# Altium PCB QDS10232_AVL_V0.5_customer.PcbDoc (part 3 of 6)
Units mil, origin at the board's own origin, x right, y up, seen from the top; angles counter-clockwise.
Board outline 3500 x 3799 mil, 6 copper layers (Top Layer, GND, INT1, PWR1, PWR2, Bottom Layer), stack 78.834 mil thick; 254 components, 204 nets, 7039 pads, 595 vias.
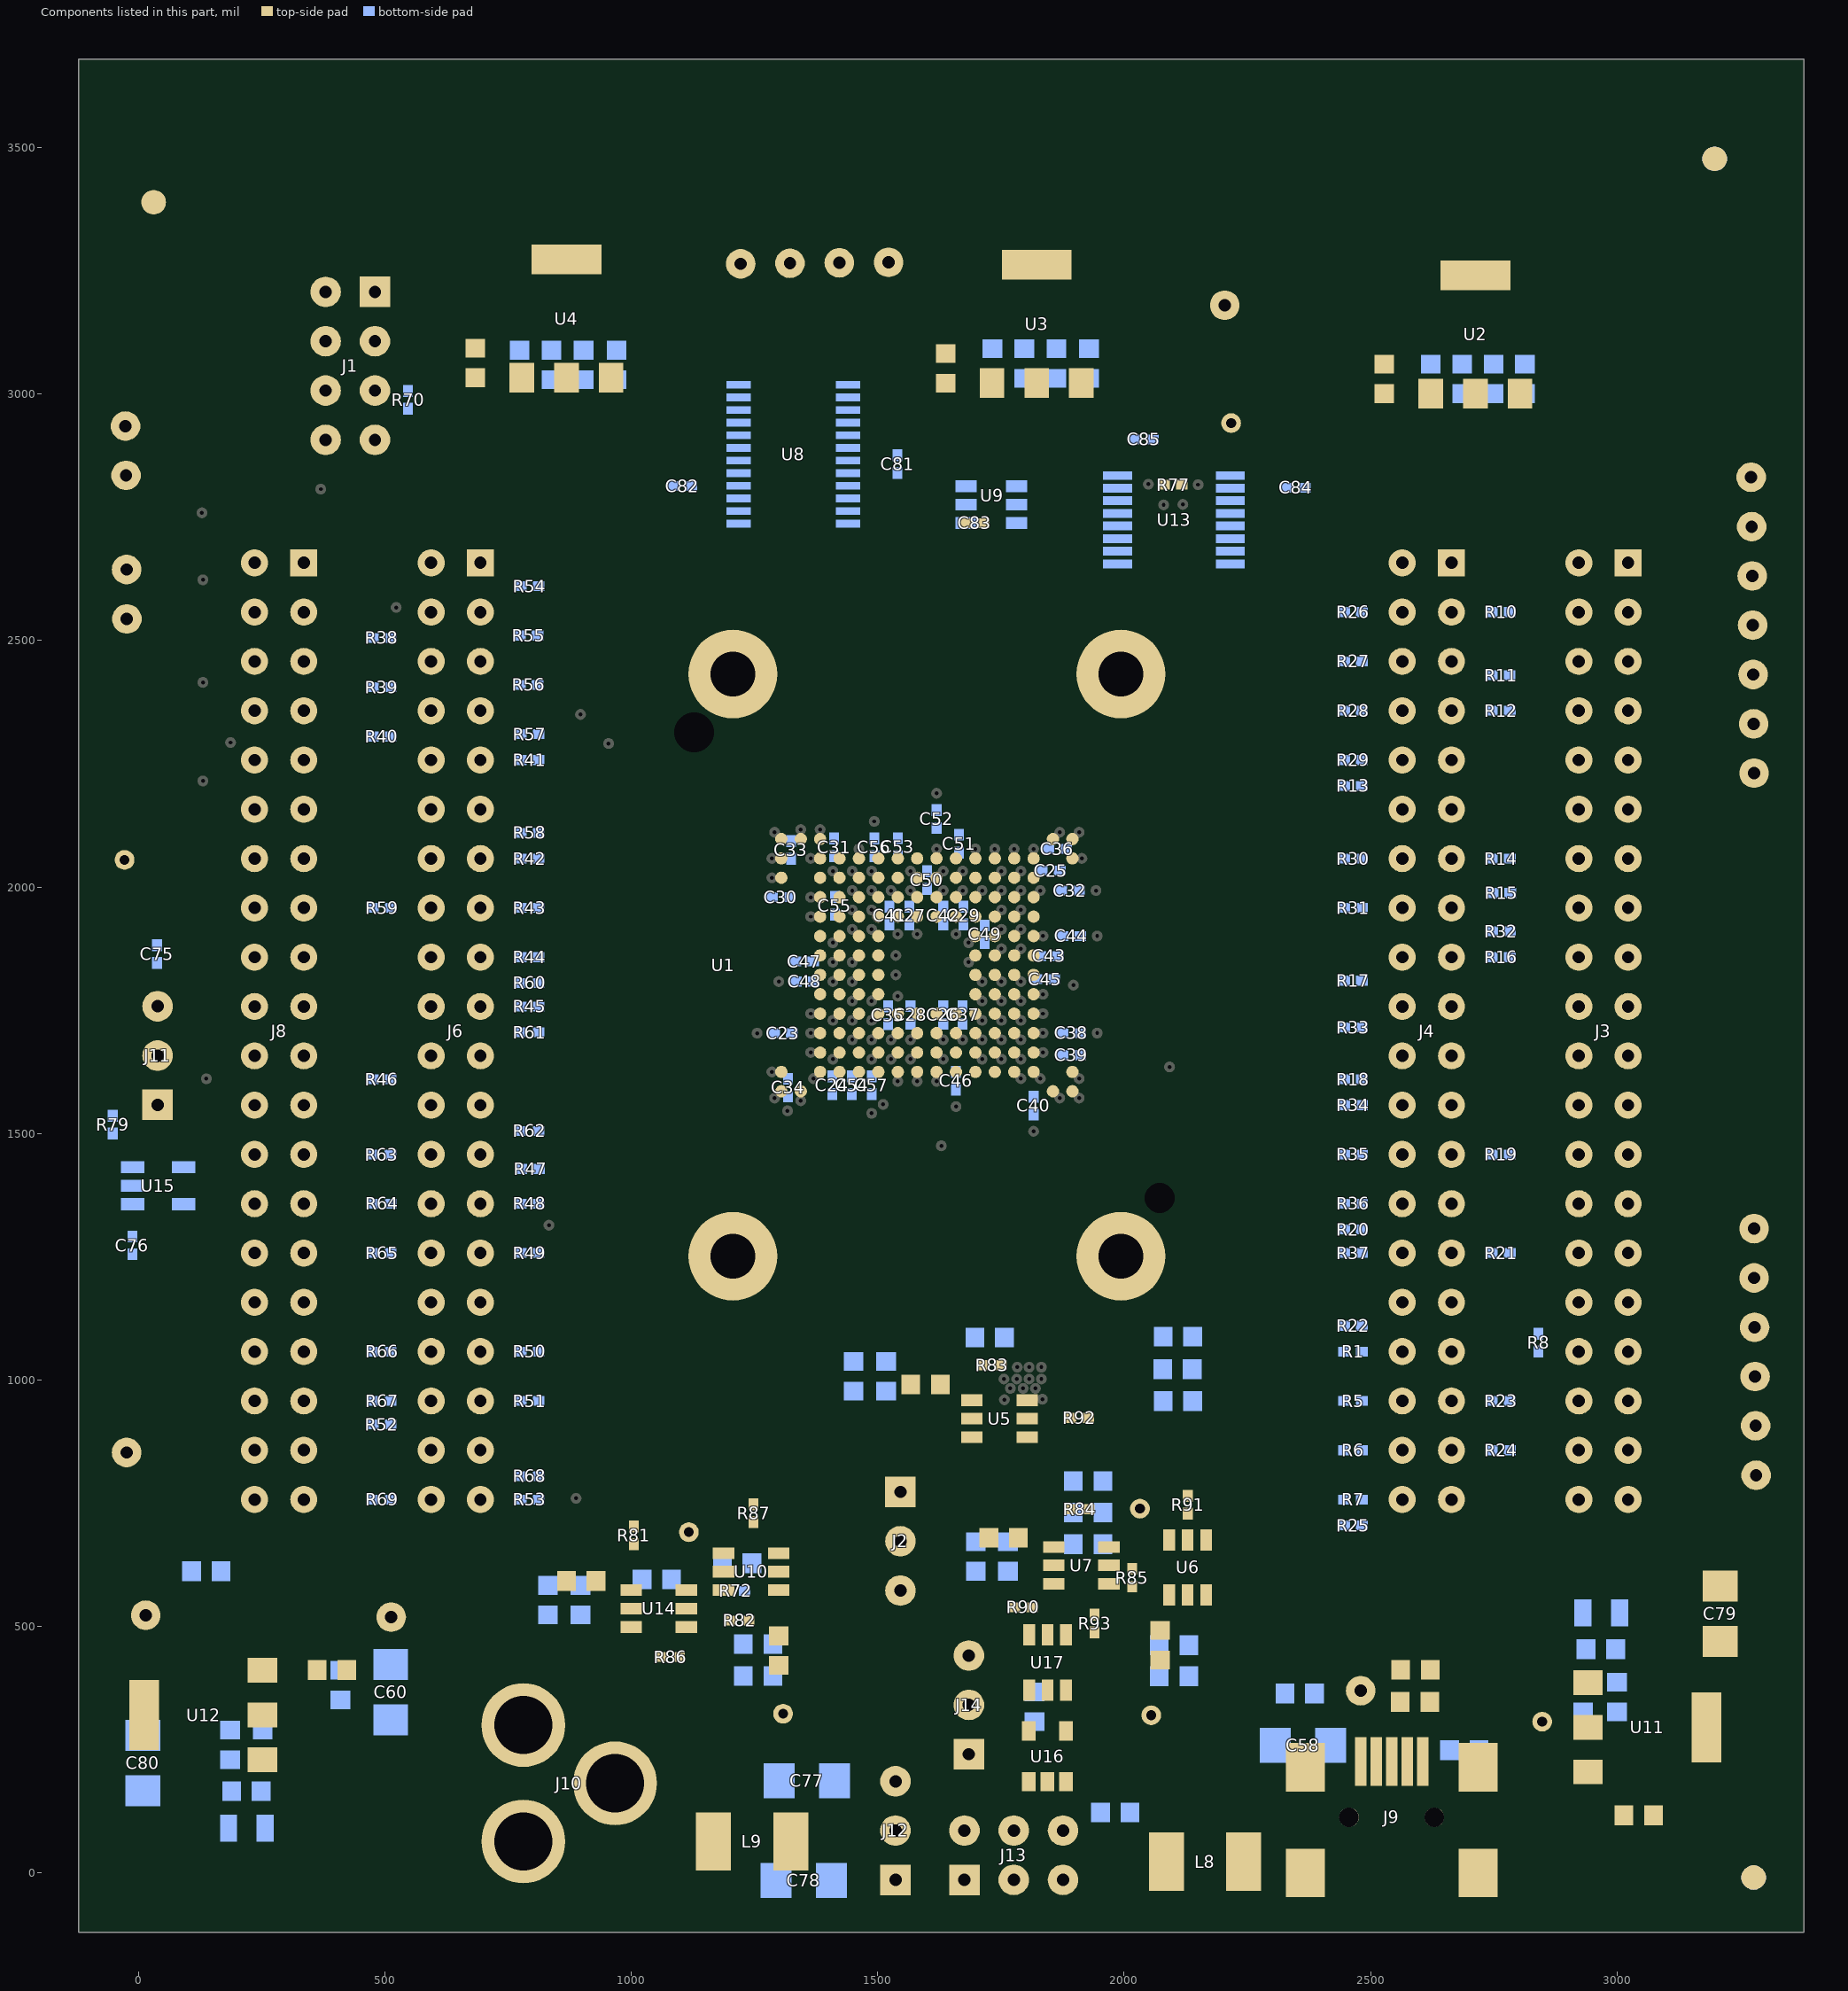
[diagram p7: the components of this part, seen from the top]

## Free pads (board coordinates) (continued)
  round 1.54 on Bottom Overlay: ""(2735.7,3575.61) ""(2735.72,3556.48) ""(2735.72,3556.48) ""(2735.72,3556.48) ""(2735.72,3556.48) ""(2735.79,3579.35) ""(2735.79,3579.35) ""(2735.79,3579.35) ""(2735.79,3579.35) ""(2735.85,3554.11) ""(2735.85,3554.11) ""(2735.85,3554.11) ""(2735.85,3554.11) ""(2736.24,3582.87) ""(2736.24,3582.87) ""(2736.24,3582.87) ""(2736.24,3582.87) ""(2736.25,3576.89) ""(2736.25,3576.89) ""(2736.25,3576.89) ""(2736.25,3576.89) ""(2736.25,3577.98) ""(2736.25,3577.98) ""(2736.25,3577.98) ""(2736.25,3577.98) ""(2736.35,3554.2) ""(2736.35,3554.2) ""(2736.35,3554.2) ""(2736.35,3554.2) ""(2736.52,3567.14) ""(2736.52,3567.14) ""(2736.52,3567.14) ""(2736.52,3567.14) ""(2736.89,3554.39) ""(2736.89,3554.39) ""(2736.89,3554.39) ""(2736.89,3554.39) ""(2737.03,3557.18) ""(2737.03,3557.18) ""(2737.03,3557.18) ""(2737.03,3557.18) ""(2737.46,3557.55) ""(2737.46,3557.55) ""(2737.46,3557.55) ""(2737.46,3557.55) ""(2737.62,3582.18) ""(2737.62,3582.18) ""(2737.62,3582.18) ""(2737.62,3582.18) ""(2737.98,3558.03) ""(2737.98,3558.03) ""(2737.98,3558.03) ""(2737.98,3558.03) ""(2738.17,3555.12) ""(2738.17,3555.12) ""(2738.17,3555.12) ""(2738.17,3555.12) ""(2738.35,3568.42) ""(2738.35,3568.42) ""(2738.35,3568.42) ""(2738.35,3568.42) ""(2738.55,3555.37) ""(2738.55,3555.37) ""(2738.55,3555.37) ""(2738.55,3555.37) ""(2738.62,3559.04) ""(2738.62,3559.04) ""(2738.81,3555.48) ""(2738.81,3555.48) ""(2738.81,3555.48) ""(2738.81,3555.48) ""(2739.07,3555.48) ""(2739.07,3555.48) ""(2739.07,3555.48) ""(2739.07,3555.48) ""(2739.08,3581.17) ""(2739.08,3581.17) ""(2739.08,3581.17) ""(2739.08,3581.17) ""(2739.35,3560.4) ""(2739.35,3560.4) ""(2739.35,3560.4) ""(2739.35,3560.4) ""(2739.38,3555.41) ""(2739.38,3555.41) ""(2739.38,3555.41) ""(2739.38,3555.41) ""(2739.46,3555.39) ""(2739.46,3555.39) ""(2739.59,3561.29) ""(2739.59,3561.29) ""(2739.59,3561.29) ""(2739.59,3561.29) ""(2739.59,3561.29) ""(2739.81,3569.51) ""(2739.81,3569.51) ""(2739.81,3569.51) ""(2739.81,3569.51) ""(2739.89,3555.01) ""(2739.89,3555.01) ""(2739.89,3555.01) ""(2739.89,3555.01) ""(2740.34,3561.86) ""(2740.34,3561.86) ""(2740.34,3561.86) ""(2740.34,3561.86) ""(2740.34,3561.86) ""(2740.5,3554.59) ""(2740.5,3554.59) ""(2740.5,3554.59) ""(2740.54,3579.71) ""(2740.54,3579.71) ""(2740.54,3579.71) ""(2740.54,3579.71) ""(2740.72,3554.57) ""(2740.72,3554.57) ""(2740.72,3554.57) ""(2740.72,3554.57) ""(2740.72,3561.86) ""(2740.72,3561.86) ""(2740.72,3561.86) ""(2740.72,3561.86) ""(2740.99,3570.69) ""(2740.99,3570.69) ""(2740.99,3570.69) ""(2740.99,3570.69) ""(2741.36,3578.35) ""(2741.36,3578.35) ""(2741.36,3578.35) ""(2741.36,3578.35) ""(2741.81,3572.15) ""(2741.81,3572.15) ""(2741.81,3572.15) ""(2741.81,3572.15) ""(2741.99,3574.7) ""(2741.99,3574.7) ""(2741.99,3576.52) ""(2741.99,3576.52) ""(2741.99,3574.7) ""(2741.99,3574.7) ""(2741.99,3576.52) ""(2741.99,3576.52) ""(2742.27,3555.34) ""(2742.27,3555.34) ""(2742.27,3555.34) ""(2742.27,3561.09) ""(2742.27,3561.09) ""(2742.27,3561.09) ""(2742.27,3555.34) ""(2742.27,3555.34) ""(2742.27,3561.09) ""(2742.27,3561.09) ""(2752.59,3555.39) ""(2752.59,3555.39) ""(2752.59,3555.39) ""(2752.59,3555.39) ""(2752.59,3555.69) ""(2752.59,3555.69) ""(2752.59,3555.69) ""(2752.59,3555.69) ""(2753.12,3556.42) ""(2753.12,3556.42) ""(2753.12,3556.42) ""(2753.12,3556.42) ""(2753.36,3554.62) ""(2753.36,3554.62) ""(2753.36,3554.62) ""(2753.36,3554.62) ""(2753.56,3556.57) ""(2753.56,3556.57) ""(2753.56,3556.57) ""(2753.56,3556.57) ""(2754.15,3556.7) ""(2754.15,3556.7) ""(2754.15,3556.7) ""(2754.15,3556.7) ""(2754.45,3556.99) ""(2754.45,3556.99) ""(2754.45,3556.99) ""(2754.45,3556.99) ""(2754.66,3557.25) ""(2754.66,3557.25) ""(2754.66,3557.25) ""(2754.66,3557.25) ""(2754.91,3557.71) ""(2754.91,3557.71) ""(2754.91,3557.71) ""(2754.91,3557.71) ""(2755.04,3558.22) ""(2755.04,3558.22) ""(2755.04,3558.22) ""(2755.04,3558.22) ""(2755.04,3570.35) ""(2755.04,3570.35) ""(2755.04,3570.35) ""(2755.04,3570.35) ""(2755.06,3570.91) ""(2755.06,3570.91) ""(2755.06,3570.91) ""(2755.06,3570.91) ""(2755.17,3571.3) ""(2755.17,3571.3) ""(2755.17,3571.3) ""(2755.17,3571.3) ""(2755.61,3572.37) ""(2755.61,3572.37) ""(2755.61,3572.37) ""(2755.61,3572.37) ""(2756.07,3573.17) ""(2756.07,3573.17) ""(2756.07,3573.17) ""(2756.07,3573.17) ""(2756.51,3573.64) ""(2756.51,3573.64) ""(2756.51,3573.64) ""(2756.51,3573.64) ""(2757.69,3574.29) ""(2757.69,3574.29) ""(2757.69,3574.29) ""(2757.69,3574.29) ""(2759.33,3574.8) ""(2759.33,3574.8) ""(2759.33,3574.8) ""(2759.33,3574.8) ""(2760.98,3574.8) ""(2760.98,3574.8) ""(2760.98,3574.8) ""(2760.98,3574.8) ""(2761.02,3557.93) ""(2761.02,3557.93) ""(2761.06,3557.37) ""(2761.06,3557.37) ""(2761.06,3569.53) ""(2761.06,3569.53) ""(2761.06,3557.37) ""(2761.06,3557.37) ""(2761.06,3569.53) ""(2761.06,3569.53) ""(2761.23,3557.12) ""(2761.23,3557.12) ""(2761.23,3557.12) ""(2761.23,3557.12) ""(2761.23,3570.04) ""(2761.23,3570.04) ""(2761.23,3570.04) ""(2761.23,3570.04) ""(2761.27,3554.62) ""(2761.27,3554.62) ""(2761.27,3554.62) ""(2761.27,3554.62) ""(2761.44,3570.38) ""(2761.44,3570.38) ""(2761.44,3570.38) ""(2761.44,3570.38) ""(2761.53,3556.78) ""(2761.53,3556.78) ""(2761.53,3556.78) ""(2761.53,3556.78) ""(2761.7,3556.7) ""(2761.7,3556.7) ""(2761.7,3556.7) ""(2761.7,3556.7) ""(2761.78,3570.89) ""(2761.78,3570.89) ""(2761.78,3570.89) ""(2761.78,3570.89) ""(2762.23,3554.62) ""(2762.23,3554.62) ""(2762.23,3554.62) ""(2762.23,3554.62) ""(2762.23,3556.7) ""(2762.23,3556.7) ""(2762.23,3556.7) ""(2762.23,3556.7) ""(2762.33,3571.27) ""(2762.33,3571.27) ""(2762.33,3571.27) ""(2762.33,3571.27) ""(2762.93,3574.56) ""(2762.93,3574.56) ""(2762.93,3574.56) ""(2762.93,3574.56) ""(2762.97,3571.61) ""(2762.97,3571.61) ""(2762.97,3571.61) ""(2762.97,3571.61) ""(2763,3555.39) ""(2763,3555.39) ""(2763,3555.39) ""(2763,3555.39) ""(2763,3555.93) ""(2763,3555.93) ""(2763,3555.93) ""(2763,3555.93) ""(2763.57,3574.48) ""(2763.57,3574.48) ""(2763.57,3574.48) ""(2763.57,3574.48) ""(2763.78,3571.79) ""(2763.78,3571.79) ""(2763.78,3571.79) ""(2763.78,3571.79) ""(2764.26,3571.74) ""(2764.26,3571.74) ""(2764.26,3571.74) ""(2764.26,3571.74) ""(2764.36,3574.25) ""(2764.36,3574.25) ""(2764.36,3574.25) ""(2764.36,3574.25) ""(2764.54,3555.35) ""(2764.54,3555.35) ""(2764.54,3555.35) ""(2764.54,3555.35) ""(2764.54,3555.74) ""(2764.54,3555.74) ""(2764.54,3555.74) ""(2764.54,3555.74) ""(2764.56,3571.7) ""(2764.56,3571.7) ""(2764.56,3571.7) ""(2764.56,3571.7) ""(2764.9,3571.56) ""(2764.9,3571.56) ""(2764.9,3571.56) ""(2764.9,3571.56) ""(2765,3573.94) ""(2765,3573.94) ""(2765,3573.94) ""(2765,3573.94) ""(2765.15,3571.39) ""(2765.15,3571.39) ""(2765.15,3571.39) ""(2765.15,3571.39) ""(2765.23,3556.51) ""(2765.23,3556.51) ""(2765.23,3556.51) ""(2765.23,3556.51) ""(2765.31,3554.58) ""(2765.43,3571.2) ""(2765.43,3571.2) ""(2765.43,3571.2) ""(2765.43,3571.2) ""(2765.58,3573.57) ""(2765.58,3573.57) ""(2765.58,3573.57) ""(2765.58,3573.57) ""(2765.7,3571.14) ""(2765.7,3571.14) ""(2765.7,3571.14) ""(2765.7,3571.14) ""(2765.85,3556.57) ""(2765.85,3556.57) ""(2765.85,3556.57) ""(2765.85,3556.57) ""(2765.96,3571.21) ""(2765.96,3571.21) ""(2765.96,3571.21) ""(2765.96,3571.21) ""(2766.05,3573.24) ""(2766.05,3573.24) ""(2766.05,3573.24) ""(2766.05,3573.24) ""(2766.23,3556.66) ""(2766.23,3556.66) ""(2766.23,3556.66) ""(2766.23,3556.66) ""(2766.31,3572.89) ""(2766.31,3572.89) ""(2766.31,3572.89) ""(2766.31,3572.89) ""(2766.35,3571.18) ""(2766.35,3571.18) ""(2766.35,3571.18) ""(2766.35,3571.18) ""(2766.44,3556.87) ""(2766.44,3556.87) ""(2766.44,3556.87) ""(2766.44,3556.87) ""(2766.57,3572.5) ""(2766.57,3572.5) ""(2766.57,3572.5) ""(2766.57,3572.5) ""(2766.6,3570.96) ""(2766.6,3570.96) ""(2766.6,3570.96) ""(2766.6,3570.96) ""(2766.65,3572.43) ""(2766.65,3572.43) ""(2766.65,3572.43) ""(2766.65,3572.43) ""(2766.7,3557.16) ""(2766.7,3557.16) ""(2766.7,3557.16) ""(2766.7,3557.16) ""(2766.8,3570.65) ""(2766.8,3570.65) ""(2766.8,3570.65) ""(2766.8,3570.65) ""(2766.82,3572.33) ""(2766.82,3572.33) ""(2766.82,3572.33) ""(2766.82,3572.33) ""(2766.82,3557.59) ""(2766.82,3557.59) ""(2766.82,3557.59) ""(2766.82,3557.59) ""(2766.91,3558.14) ""(2766.91,3558.14) ""(2766.91,3569.02) ""(2766.91,3569.02) ""(2766.91,3570.34) ""(2766.91,3570.34) ""(2766.91,3558.14) ""(2766.91,3558.14) ""(2766.91,3569.02) ""(2766.91,3569.02) ""(2766.91,3570.34) ""(2766.91,3570.34) ""(2766.94,3572.29) ""(2766.94,3572.29) ""(2766.94,3572.29) ""(2766.94,3572.29) ""(2767.04,3572.28) ""(2767.04,3572.28) ""(2767.04,3572.28) ""(2767.04,3572.28) ""(2767.16,3572.3) ""(2767.16,3572.3) ""(2767.16,3572.3) ""(2767.16,3572.3) ""(2767.28,3572.49) ""(2767.28,3572.49) ""(2767.28,3572.49) ""(2767.28,3572.49) ""(2767.3,3572.58) ""(2767.3,3572.58) ""(2767.3,3572.58) ""(2767.3,3572.58) ""(2767.3,3573.38) ""(2767.3,3573.38) ""(2767.3,3573.38) ""(2767.3,3573.38) ""(2768.07,3574.15) ""(2768.07,3574.15) ""(2768.07,3574.15) ""(2768.07,3574.15) ""(2773.06,3558.65) ""(2773.06,3558.65) ""(2773.06,3558.65) ""(2773.06,3558.65) ""(2773.06,3570.42) ""(2773.06,3570.42) ""(2773.06,3570.42) ""(2773.06,3570.42) ""(2773.14,3570.84) ""(2773.14,3570.84) ""(2773.18,3557.67) ""(2773.18,3557.67) ""(2773.35,3557.33) ""(2773.35,3557.33) ""(2773.35,3557.33) ""(2773.35,3557.33) ""(2773.39,3571.23) ""(2773.39,3571.23) ""(2773.39,3571.23) ""(2773.39,3571.23) ""(2773.73,3556.99) ""(2773.73,3556.99) ""(2773.73,3556.99) ""(2773.73,3556.99) ""(2773.78,3571.52) ""(2773.78,3571.52) ""(2773.78,3571.52) ""(2773.78,3571.52) ""(2774.16,3571.69) ""(2774.16,3571.69) ""(2774.16,3571.69) ""(2774.16,3571.69) ""(2774.2,3556.66) ""(2774.2,3556.66) ""(2774.2,3556.66) ""(2774.2,3556.66) ""(2774.45,3554.58) ""(2774.45,3554.58) ""(2774.45,3554.58) ""(2774.45,3554.58) ""(2774.67,3571.78) ""(2774.67,3571.78) ""(2774.67,3571.78) ""(2774.67,3571.78) ""(2774.71,3556.47) ""(2774.71,3556.47) ""(2774.71,3556.47) ""(2774.71,3556.47) ""(2775.01,3571.86) ""(2775.01,3571.86) ""(2775.01,3571.86) ""(2775.01,3571.86) ""(2775.13,3574.06) ""(2775.13,3574.06) ""(2775.13,3574.06) ""(2775.13,3574.06) ""(2775.18,3572.03) ""(2775.18,3572.03) ""(2775.18,3572.03) ""(2775.18,3572.03) ""(2775.22,3555.35) ""(2775.22,3555.35) ""(2775.22,3555.35) ""(2775.22,3555.35) ""(2775.22,3555.75) ""(2775.22,3555.75) ""(2775.22,3555.75) ""(2775.22,3555.75) ""(2775.26,3572.37) ""(2775.26,3572.37) ""(2775.26,3572.37) ""(2775.26,3572.37) ""(2775.26,3573.81) ""(2775.26,3573.81) ""(2775.26,3573.81) ""(2775.26,3573.81) ""(2778.64,3574.09) ""(2778.64,3574.09) ""(2778.64,3574.09) ""(2778.64,3574.09) ""(2778.78,3575.82) ""(2778.78,3575.82) ""(2778.78,3575.82) ""(2778.78,3575.82) ""(2779.05,3552.78) ""(2779.05,3552.78) ""(2779.05,3576.31) ""(2779.05,3576.31) ""(2779.05,3552.78) ""(2779.05,3552.78) ""(2779.05,3576.31) ""(2779.05,3576.31) ""(2779.19,3551.4) ""(2779.19,3551.4) ""(2779.19,3551.4) ""(2779.19,3551.4) ""(2779.26,3572.78) ""(2779.26,3572.78) ""(2779.26,3572.78) ""(2779.26,3572.78) ""(2779.4,3554.51) ""(2779.4,3554.51) ""(2779.4,3554.51) ""(2779.4,3554.51) ""(2779.61,3572.57) ""(2779.61,3572.57) ""(2779.61,3572.57) ""(2779.61,3572.57) ""(2779.68,3576.86) ""(2779.68,3576.86) ""(2779.68,3576.86) ""(2779.68,3576.86) ""(2779.74,3549.88) ""(2779.74,3549.88) ""(2779.74,3549.88) ""(2779.74,3549.88) ""(2779.95,3555.41) ""(2779.95,3555.41) ""(2779.95,3555.41) ""(2779.95,3555.41) ""(2780.23,3572.43) ""(2780.23,3572.43) ""(2780.23,3577.27) ""(2780.23,3577.27) ""(2780.23,3572.43) ""(2780.23,3572.43) ""(2780.23,3577.27) ""(2780.23,3577.27) ""(2780.44,3566.55) ""(2780.44,3566.55) ""(2780.44,3566.55) ""(2780.44,3566.55) ""(2780.58,3568.14) ""(2780.58,3568.14) ""(2780.58,3568.14) ""(2780.58,3568.14) ""(2780.64,3564.96) ""(2780.64,3564.96) ""(2780.64,3564.96) ""(2780.64,3564.96) ""(2780.78,3569.53) ""(2780.78,3569.53) ""(2780.78,3569.53) ""(2780.78,3569.53) ""(2780.92,3572.43) ""(2780.92,3572.43) ""(2780.92,3572.43) ""(2780.92,3572.43) ""(2780.92,3577.55) ""(2780.92,3577.55) ""(2780.92,3577.55) ""(2780.92,3577.55) ""(2780.99,3548.35) ""(2780.99,3548.35) ""(2780.99,3548.35) ""(2780.99,3548.35) ""(2781.27,3556.66) ""(2781.27,3556.66) ""(2781.27,3556.66) ""(2781.27,3556.66) ""(2781.27,3563.3) ""(2781.27,3563.3) ""(2781.27,3563.3) ""(2781.27,3563.3) ""(2781.41,3572.43) ""(2781.41,3572.43) ""(2781.41,3572.43) ""(2781.41,3572.43) ""(2781.48,3570.77) ""(2781.48,3570.77) ""(2781.48,3570.77) ""(2781.48,3570.77) ""(2781.75,3572.64) ""(2781.75,3572.64) ""(2781.75,3572.64) ""(2781.75,3572.64) ""(2781.89,3573.12) ""(2781.89,3573.12) ""(2781.89,3573.12) ""(2781.89,3573.12) ""(2781.89,3573.4) ""(2781.89,3573.4) ""(2781.89,3573.4) ""(2781.89,3573.4) ""(2781.96,3562.47) ""(2781.96,3562.47) ""(2781.96,3573.68) ""(2781.96,3573.68) ""(2781.96,3562.47) ""(2781.96,3562.47) ""(2781.96,3573.68) ""(2781.96,3573.68) ""(2782.1,3571.53) ""(2782.1,3571.53) ""(2782.1,3571.53) ""(2782.1,3571.53) ""(2782.1,3577.48) ""(2782.1,3577.48) ""(2782.1,3577.48) ""(2782.1,3577.48) ""(2782.38,3574.02) ""(2782.38,3574.02) ""(2782.38,3574.02) ""(2782.38,3574.02) ""(2782.72,3557.49) ""(2782.72,3557.49) ""(2782.72,3557.49) ""(2782.72,3557.49) ""(2782.79,3546.97) ""(2782.79,3546.97) ""(2782.79,3546.97) ""(2782.79,3546.97) ""(2782.79,3574.02) ""(2782.79,3574.02) ""(2782.79,3574.02) ""(2782.79,3574.02) ""(2782.79,3577.27) ""(2782.79,3577.27) ""(2782.79,3577.27) ""(2782.79,3577.27) ""(2783.07,3572.22) ""(2783.07,3572.22) ""(2783.07,3572.22) ""(2783.07,3572.22) ""(2783.07,3573.75) ""(2783.07,3573.75) ""(2783.07,3573.75) ""(2783.07,3573.75) ""(2783.34,3576.86) ""(2783.34,3576.86) ""(2783.35,3576.86) ""(2783.35,3576.86) ""(2783.41,3561.15) ""(2783.41,3561.15) ""(2783.41,3561.15) ""(2783.41,3561.15) ""(2783.9,3557.97) ""(2783.9,3557.97) ""(2783.9,3557.97) ""(2783.9,3557.97) ""(2783.9,3576.31) ""(2783.9,3576.31) ""(2783.9,3576.31) ""(2783.9,3576.31) ""(2784.25,3574.02) ""(2784.25,3574.02) ""(2784.25,3574.02) ""(2784.25,3574.02) ""(2784.25,3574.58) ""(2784.25,3574.58) ""(2784.25,3574.58) ""(2784.25,3574.58) ""(2784.25,3575.48) ""(2784.25,3575.48) ""(2784.25,3575.48) ""(2784.25,3575.48) ""(2784.38,3573.75) ""(2784.38,3573.75) ""(2784.38,3573.75) ""(2784.38,3573.75) ""(2784.45,3546.14) ""(2784.45,3546.14) ""(2784.45,3546.14) ""(2784.45,3546.14) ""(2784.73,3550.43) ""(2784.73,3550.43) ""(2784.73,3573.61) ""(2784.73,3573.61) ""(2784.73,3550.43) ""(2784.73,3550.43) ""(2784.73,3573.61) ""(2784.73,3573.61) ""(2784.8,3551.05) ""(2784.8,3551.05) ""(2784.8,3551.05) ""(2784.8,3551.05) ""(2784.87,3560.25) ""(2784.87,3560.25) ""(2784.87,3560.25) ""(2784.87,3560.25) ""(2784.94,3551.61) ""(2784.94,3551.61) ""(2784.94,3551.61) ""(2784.94,3551.61) ""(2785.01,3549.95) ""(2785.01,3549.95) ""(2785.01,3549.95) ""(2785.01,3549.95) ""(2785.22,3551.95) ""(2785.22,3551.95) ""(2785.22,3551.95) ""(2785.22,3551.95) ""(2785.42,3573.95) ""(2785.42,3573.95) ""(2785.42,3573.95) ""(2785.42,3573.95) ""(2785.56,3549.39) ""(2785.56,3549.39) ""(2785.56,3549.39) ""(2785.56,3549.39) ""(2785.77,3552.37) ""(2785.77,3552.37) ""(2786.18,3548.91) ""(2786.18,3548.91) ""(2786.18,3548.91) ""(2786.18,3548.91) ""(2786.32,3558.25) ""(2786.32,3558.25) ""(2786.32,3558.25) ""(2786.32,3558.25) ""(2786.46,3574.78) ""(2786.46,3574.78) ""(2786.46,3574.78) ""(2786.46,3574.78) ""(2786.81,3559.91) ""(2786.81,3559.91) ""(2786.81,3559.91) ""(2786.81,3559.91) ""(2786.88,3564.54) ""(2786.88,3564.54) ""(2786.88,3564.54) ""(2786.88,3564.54) ""(2786.88,3569.53) ""(2786.88,3569.53) ""(2786.88,3569.53) ""(2786.88,3569.53) ""(2786.89,3570.47) ""(2786.89,3570.47) ""(2786.89,3570.47) ""(2786.89,3570.47) ""(2786.95,3545.73) ""(2786.95,3545.73) ""(2786.95,3574.92) ""(2786.95,3574.92) ""(2786.95,3545.73) ""(2786.95,3545.73) ""(2786.95,3574.92) ""(2786.95,3574.92) ""(2787.02,3548.49) ""(2787.02,3548.49) ""(2787.02,3548.49) ""(2787.02,3548.49) ""(2787.06,3571.19) ""(2787.06,3571.19) ""(2787.06,3571.19) ""(2787.06,3571.19) ""(2787.08,3563.47) ""(2787.08,3563.47) ""(2787.08,3563.47) ""(2787.08,3563.47) ""(2787.08,3553.2) ""(2787.08,3553.2) ""(2787.08,3553.2) ""(2787.08,3553.2) ""(2787.29,3562.92) ""(2787.29,3562.92) ""(2787.29,3562.92) ""(2787.29,3562.92) ""(2787.38,3571.97) ""(2787.38,3571.97) ""(2787.38,3571.97) ""(2787.38,3571.97) ""(2787.66,3562.43) ""(2787.66,3562.43) ""(2787.66,3562.43) ""(2787.66,3562.43) ""(2787.78,3572.42) ""(2787.78,3572.42) ""(2787.78,3572.42) ""(2787.78,3572.42) ""(2787.93,3562.15) ""(2787.93,3562.15) ""(2787.93,3562.15) ""(2787.93,3562.15) ""(2788.05,3548.15) ""(2788.05,3548.15) ""(2788.05,3548.15) ""(2788.05,3548.15) ""(2788.19,3553.47) ""(2788.19,3553.47) ""(2788.19,3553.47) ""(2788.19,3553.47) ""(2788.26,3575.34) ""(2788.26,3575.34) ""(2788.26,3575.34) ""(2788.26,3575.34) ""(2788.33,3561.9) ""(2788.33,3561.9) ""(2788.33,3561.9) ""(2788.33,3561.9) ""(2788.35,3572.73) ""(2788.35,3572.73) ""(2788.35,3572.73) ""(2788.35,3572.73) ""(2788.4,3559.63) ""(2788.4,3559.63) ""(2788.4,3559.63) ""(2788.4,3559.63) ""(2789.01,3572.88) ""(2789.01,3572.88) ""(2789.01,3572.88) ""(2789.01,3572.88) ""(2789.09,3547.87) ""(2789.09,3547.87) ""(2789.09,3547.87) ""(2789.09,3547.87) ""(2789.16,3545.59) ""(2789.16,3545.59) ""(2789.16,3545.59) ""(2789.16,3545.59) ""(2789.3,3553.61) ""(2789.3,3553.61) ""(2789.3,3558.25) ""(2789.3,3558.25) ""(2789.3,3553.61) ""(2789.3,3553.61) ""(2789.3,3558.25) ""(2789.3,3558.25) ""(2789.44,3561.71) ""(2789.44,3561.71) ""(2789.44,3561.71) ""(2789.44,3561.71) ""(2789.5,3572.88) ""(2789.5,3572.88) ""(2789.5,3572.88) ""(2789.5,3572.88) ""(2790.06,3559.7) ""(2790.06,3559.7) ""(2790.06,3559.7) ""(2790.06,3559.7) ""(2790.06,3575.34) ""(2790.06,3575.34) ""(2790.06,3575.34) ""(2790.06,3575.34) ""(2790.07,3572.73) ""(2790.07,3572.73) ""(2790.07,3572.73) ""(2790.07,3572.73) ""(2790.13,3547.59) ""(2790.13,3547.59) ""(2790.13,3553.68) ""(2790.13,3553.68) ""(2790.13,3547.59) ""(2790.13,3547.59) ""(2790.13,3553.68) ""(2790.13,3553.68) ""(2790.2,3561.91) ""(2790.2,3561.91) ""(2790.2,3561.91) ""(2790.2,3561.91) ""(2790.66,3572.5) ""(2790.66,3572.5) ""(2790.66,3572.5) ""(2790.66,3572.5) ""(2790.76,3562.4) ""(2790.76,3562.4) ""(2790.76,3562.4) ""(2790.76,3562.4) ""(2791.07,3572.27) ""(2791.07,3572.27) ""(2791.07,3572.27) ""(2791.07,3572.27) ""(2791.1,3558.04) ""(2791.1,3558.04) ""(2791.1,3558.04) ""(2791.1,3558.04) ""(2791.17,3562.81) ""(2791.17,3562.81) ""(2791.17,3562.81) ""(2791.17,3562.81) ""(2791.24,3553.61) ""(2791.24,3553.61) ""(2791.24,3553.61) ""(2791.24,3553.61) ""(2791.38,3547.52) ""(2791.38,3547.52) ""(2791.38,3547.52) ""(2791.38,3547.52) ""(2791.38,3571.86) ""(2791.38,3571.86) ""(2791.39,3571.86) ""(2791.39,3571.86) ""(2791.59,3559.84) ""(2791.59,3559.84) ""(2791.59,3559.84) ""(2791.59,3559.84) ""(2791.59,3563.51) ""(2791.59,3563.51) ""(2791.59,3563.51) ""(2791.59,3563.51) ""(2791.64,3571.4) ""(2791.64,3571.4) ""(2791.64,3571.4) ""(2791.64,3571.4) ""(2791.66,3545.86) ""(2791.66,3545.86) ""(2791.66,3545.86) ""(2791.66,3545.86) ""(2791.72,3571) ""(2791.72,3571) ""(2791.72,3571) ""(2791.72,3571) ""(2791.72,3564.27) ""(2791.72,3564.27) ""(2791.72,3570.43) ""(2791.72,3570.43) ""(2791.72,3564.27) ""(2791.72,3564.27) ""(2791.72,3570.43) ""(2791.72,3570.43) ""(2792.35,3547.87) ""(2792.35,3547.87) ""(2792.35,3547.87) ""(2792.35,3547.87) ""(2792.35,3557.83) ""(2792.35,3557.83) ""(2792.35,3557.83) ""(2792.35,3557.83) ""(2792.35,3560.05) ""(2792.35,3560.05) ""(2792.35,3560.05) ""(2792.35,3560.05) ""(2792.49,3575.2) ""(2792.49,3575.2) ""(2792.49,3575.2) ""(2792.49,3575.2) ""(2792.56,3550.15) ""(2792.56,3550.15) ""(2792.56,3550.15) ""(2792.56,3550.15) ""(2792.56,3550.98) ""(2792.56,3550.98) ""(2792.56,3550.98) ""(2792.56,3550.98) ""(2792.76,3548.22) ""(2792.76,3548.22) ""(2792.76,3549.81) ""(2792.76,3549.81) ""(2792.76,3551.4) ""(2792.76,3551.4) ""(2792.76,3553.41) ""(2792.76,3553.41) ""(2792.76,3559.84) ""(2792.76,3559.84) ""(2792.76,3548.22) ""(2792.76,3548.22) ""(2792.76,3549.81) ""(2792.76,3549.81) ""(2792.76,3551.4) ""(2792.76,3551.4) ""(2792.76,3553.41) ""(2792.76,3553.41) ""(2792.76,3559.84) ""(2792.76,3559.84) ""(2792.97,3548.49) ""(2792.97,3548.49) ""(2792.97,3548.49) ""(2792.97,3548.49) ""(2792.97,3549.18) ""(2792.97,3549.18) ""(2792.97,3549.18) ""(2792.97,3549.18) ""(2793.04,3551.74) ""(2793.04,3551.74) ""(2793.04,3551.74) ""(2793.04,3551.74) ""(2793.11,3548.91) ""(2793.11,3548.91) ""(2793.11,3548.91) ""(2793.11,3548.91) ""(2793.46,3574.64) ""(2793.46,3574.64) ""(2793.46,3574.64) ""(2793.46,3574.64) ""(2793.52,3557.56) ""(2793.52,3557.56) ""(2793.52,3557.56) ""(2793.52,3557.56) ""(2793.66,3552.23) ""(2793.66,3552.23) ""(2793.66,3552.23) ""(2793.66,3552.23) ""(2793.8,3546.14) ""(2793.8,3546.14) ""(2793.8,3546.14) ""(2793.8,3546.14) ""(2794.01,3553.2) ""(2794.01,3553.2) ""(2794.01,3553.2) ""(2794.01,3553.2) ""(2794.01,3557.35) ""(2794.01,3557.35) ""(2794.01,3557.35) ""(2794.01,3557.35) ""(2794.29,3557.42) ""(2794.29,3557.42) ""(2794.29,3557.42) ""(2794.29,3557.42) ""(2794.29,3557.9) ""(2794.29,3557.9) ""(2794.29,3557.9) ""(2794.29,3557.9) ""(2794.36,3552.44) ""(2794.36,3552.44) ""(2794.36,3552.44) ""(2794.36,3552.44) ""(2794.42,3557.63) ""(2794.42,3557.63) ""(2794.42,3557.63) ""(2794.42,3557.63) ""(2794.84,3552.99) ""(2794.84,3552.99) ""(2794.84,3552.99) ""(2794.84,3552.99) ""(2794.84,3560.74) ""(2794.84,3560.74) ""(2794.84,3560.74) ""(2794.84,3560.74) ""(2794.91,3552.51) ""(2794.91,3552.51) ""(2794.91,3552.51) ""(2794.91,3552.51) ""(2794.98,3560.39) ""(2794.98,3560.39) ""(2794.98,3560.39) ""(2794.98,3560.39) ""(2794.98,3573.88) ""(2794.98,3573.88) ""(2794.98,3573.88) ""(2794.98,3573.88) ""(2795.05,3561.08) ""(2795.05,3561.08) ""(2795.05,3561.08) ""(2795.05,3561.08) ""(2795.12,3546.42) ""(2795.12,3546.42) ""(2795.12,3546.42) ""(2795.12,3546.42) ""(2795.32,3561.43) ""(2795.32,3561.43) ""(2795.32,3561.43) ""(2795.32,3561.43) ""(2795.74,3552.37) ""(2795.74,3552.37) ""(2795.74,3552.37) ""(2795.74,3552.37) ""(2795.81,3552.85) ""(2795.81,3552.85) ""(2796.02,3572.85) ""(2796.02,3572.85) ""(2796.02,3572.85) ""(2796.02,3572.85) ""(2796.16,3562.12) ""(2796.16,3562.12) ""(2796.16,3562.12) ""(2796.16,3562.12) ""(2796.43,3547.18) ""(2796.43,3547.18) ""(2796.43,3547.18) ""(2796.43,3547.18) ""(2796.5,3552.02) ""(2796.5,3552.02) ""(2796.5,3552.02) ""(2796.5,3552.02) ""(2796.71,3552.71) ""(2796.71,3552.71) ""(2796.71,3552.71) ""(2796.71,3552.71) ""(2796.85,3563.09) ""(2796.85,3563.09) ""(2796.85,3563.09) ""(2796.85,3563.09) ""(2797.06,3547.8) ""(2797.06,3547.8) ""(2797.06,3571.6) ""(2797.06,3571.6) ""(2797.06,3547.8) ""(2797.06,3547.8) ""(2797.06,3571.6) ""(2797.06,3571.6) ""(2797.19,3551.68) ""(2797.19,3551.68) ""(2797.19,3551.68) ""(2797.19,3551.68) ""(2797.33,3563.85) ""(2797.33,3563.85) ""(2797.33,3563.85) ""(2797.33,3563.85) ""(2797.61,3548.29) ""(2797.61,3548.29) ""(2797.61,3548.29) ""(2797.61,3548.29) ""(2797.75,3552.44) ""(2797.75,3552.44) ""(2797.75,3552.44) ""(2797.75,3552.44) ""(2797.75,3564.68) ""(2797.75,3564.68) ""(2797.75,3564.68) ""(2797.75,3564.68) ""(2797.75,3570.49) ""(2797.75,3570.49) ""(2797.75,3570.49) ""(2797.75,3570.49) ""(2797.89,3551.19) ""(2797.89,3551.19) ""(2797.89,3551.19) ""(2797.89,3551.19) ""(2797.96,3549.18) ""(2797.96,3549.18) ""(2797.96,3549.18) ""(2797.96,3549.18) ""(2798.09,3550.15) ""(2798.09,3550.15) ""(2798.09,3550.64) ""(2798.09,3550.64) ""(2798.09,3566) ""(2798.09,3566) ""(2798.1,3550.15) ""(2798.1,3550.15) ""(2798.1,3550.64) ""(2798.1,3550.64) ""(2798.1,3566) ""(2798.1,3566) ""(2798.16,3569.11) ""(2798.16,3569.11) ""(2798.16,3569.11) ""(2798.16,3569.11) ""(2798.23,3552.51) ""(2798.23,3552.51) ""(2798.23,3552.51) ""(2798.23,3552.51) ""(2798.23,3567.59) ""(2798.23,3567.59) ""(2798.23,3567.59) ""(2798.23,3567.59) ""(2798.86,3552.78) ""(2798.86,3552.78) ""(2798.86,3552.78) ""(2798.86,3552.78) ""(2799.06,3555.07) ""(2799.06,3555.07) ""(2799.06,3555.07) ""(2799.06,3555.07) ""(2799.13,3553.06) ""(2799.13,3553.06) ""(2799.13,3553.06) ""(2799.13,3553.06) ""(2799.34,3553.75) ""(2799.34,3553.75) ""(2799.34,3553.75) ""(2799.34,3553.75) ""(2799.34,3554.23) ""(2799.34,3554.23) ""(2799.34,3554.23) ""(2799.34,3554.23) ""(2803.14,3554.94) ""(2803.14,3554.94) ""(2803.14,3554.94) ""(2803.14,3554.94) ""(2803.14,3556.95) ""(2803.14,3556.95) ""(2803.14,3556.95) ""(2803.14,3556.95) ""(2803.25,3556.95) ""(2803.25,3556.95) ""(2803.25,3556.95) ""(2803.25,3556.95) ""(2803.62,3557.05) ""(2803.62,3557.05) ""(2803.62,3557.05) ""(2803.62,3557.05) ""(2804.06,3557.21) ""(2804.06,3557.21) ""(2804.06,3557.21) ""(2804.06,3557.21) ""(2804.56,3557.94) ""(2804.56,3557.94) ""(2804.56,3557.94) ""(2804.56,3557.94) ""(2804.56,3558.54) ""(2804.56,3558.54) ""(2804.56,3558.54) ""(2804.56,3558.54) ""(2804.56,3574.1) ""(2804.56,3574.1) ""(2804.56,3574.1) ""(2804.56,3574.1) ""(2805.33,3574.87) ""(2805.33,3574.87) ""(2805.33,3574.87) ""(2805.33,3574.87) ""(2810.93,3558.33) ""(2810.93,3558.33) ""(2810.93,3558.33) ""(2810.93,3558.33) ""(2810.93,3571.2) ""(2810.93,3571.2) ""(2810.93,3571.2) ""(2810.93,3571.2) ""(2810.99,3571.54) ""(2810.99,3571.54) ""(2810.99,3571.54) ""(2810.99,3571.54) ""(2811.07,3557.78) ""(2811.07,3557.78) ""(2811.07,3557.78) ""(2811.07,3557.78) ""(2811.18,3571.75) ""(2811.18,3571.75) ""(2811.18,3571.75) ""(2811.18,3571.75) ""(2811.35,3557.44) ""(2811.35,3557.44) ""(2811.35,3557.44) ""(2811.35,3557.44) ""(2811.4,3571.99) ""(2811.4,3571.99) ""(2811.4,3571.99) ""(2811.4,3571.99) ""(2811.59,3572.14) ""(2811.59,3572.14) ""(2811.59,3572.14) ""(2811.59,3572.14) ""(2811.79,3572.3) ""(2811.79,3572.3) ""(2811.79,3572.3) ""(2811.79,3572.3) ""(2811.83,3557.09) ""(2811.83,3557.09) ""(2811.83,3557.09) ""(2811.83,3557.09) ""(2812.03,3572.39) ""(2812.03,3572.39) ""(2812.03,3572.39) ""(2812.03,3572.39) ""(2812.31,3574.87) ""(2812.31,3554.94) ""(2812.31,3554.94) ""(2812.31,3554.94) ""(2812.31,3554.94) ""(2812.31,3572.39) ""(2812.31,3572.39) ""(2812.31,3572.39) ""(2812.31,3572.39) ""(2812.31,3574.87) ""(2812.31,3574.87) ""(2812.31,3574.87) ""(2812.53,3556.88) ""(2812.53,3556.88) ""(2812.53,3556.88) ""(2812.53,3556.88) ""(2813.08,3555.72) ""(2813.08,3555.72) ""(2813.08,3555.72) ""(2813.08,3555.72) ""(2813.08,3556.14) ""(2813.08,3556.14) ""(2813.08,3556.14) ""(2813.08,3556.14) ""(2813.08,3573.16) ""(2813.08,3573.16) ""(2813.08,3573.16) ""(2813.08,3573.16) ""(2813.08,3574.1) ""(2813.08,3574.1) ""(2813.08,3574.1) ""(2813.08,3574.1) ""(2814.99,3560.44) ""(2814.99,3560.44) ""(2814.99,3560.44) ""(2814.99,3560.44) ""(2815.12,3562.26) ""(2815.12,3562.26) ""(2815.12,3562.26) ""(2815.12,3562.26) ""(2815.51,3563.69) ""(2815.51,3563.69) ""(2815.51,3563.69) ""(2815.51,3563.69) ""(2815.9,3558.37) ""(2815.9,3558.37) ""(2815.9,3558.37) ""(2815.9,3558.37) ""(2816.31,3570.38) ""(2816.31,3570.38) ""(2816.31,3570.38) ""(2816.31,3570.38) ""(2816.38,3571.07) ""(2816.38,3571.07) ""(2816.38,3571.07) ""(2816.38,3571.07) ""(2816.55,3564.86) ""(2816.55,3564.86) ""(2816.55,3564.86) ""(2816.55,3564.86) ""(2816.59,3569.68) ""(2816.59,3569.68) ""(2816.59,3569.68) ""(2816.59,3569.68) ""(2816.59,3571.76) ""(2816.59,3571.76) ""(2816.59,3571.76) ""(2816.59,3571.76) ""(2816.8,3572.38) ""(2816.8,3572.38) ""(2816.8,3572.38) ""(2816.8,3572.38) ""(2816.94,3556.94) ""(2816.94,3556.94) ""(2816.94,3556.94) ""(2816.94,3556.94) ""(2817.01,3568.99) ""(2817.01,3568.99) ""(2817.01,3568.99) ""(2817.01,3568.99) ""(2817.01,3572.94) ""(2817.01,3572.94) ""(2817.01,3572.94) ""(2817.01,3572.94) ""(2817.46,3565.64) ""(2817.46,3565.64) ""(2817.46,3565.64) ""(2817.46,3565.64) ""(2817.7,3573.56) ""(2817.7,3573.56) ""(2817.7,3573.56) ""(2817.7,3573.56) ""(2817.72,3568.5) ""(2817.72,3568.5) ""(2817.72,3568.5) ""(2817.72,3568.5) ""(2818.37,3555.9) ""(2818.37,3555.9) ""(2818.37,3555.9) ""(2818.37,3555.9) ""(2818.53,3574.04) ""(2818.53,3574.04) ""(2818.53,3574.04) ""(2818.53,3574.04) ""(2818.89,3566.29) ""(2818.89,3566.29) ""(2818.89,3566.29) ""(2818.89,3566.29) ""(2819.22,3574.46) ""(2819.22,3574.46) ""(2819.22,3574.46) ""(2819.22,3574.46) ""(2820.06,3574.74) ""(2820.06,3574.74) ""(2820.06,3574.74) ""(2820.06,3574.74) ""(2820.16,3568.5) ""(2820.16,3568.5) ""(2820.16,3568.5) ""(2820.16,3568.5) ""(2820.19,3554.99) ""(2820.19,3554.99) ""(2820.19,3554.99) ""(2820.19,3554.99) ""(2820.45,3566.81) ""(2820.45,3566.81) ""(2820.45,3566.81) ""(2820.45,3566.81) ""(2820.58,3559.02) ""(2820.58,3559.02) ""(2820.58,3559.02) ""(2820.58,3559.02) ""(2820.71,3557.46) ""(2820.71,3557.46) ""(2820.71,3557.46) ""(2820.71,3557.46) ""(2820.97,3560.05) ""(2820.97,3560.05) ""(2820.97,3560.05) ""(2820.97,3560.05) ""(2821.1,3569.15) ""(2821.1,3569.15) ""(2821.1,3569.15) ""(2821.1,3569.15) ""(2821.23,3570.97) ""(2821.23,3570.97) ""(2821.23,3571.75) ""(2821.23,3571.75) ""(2821.23,3570.97) ""(2821.23,3570.97) ""(2821.23,3571.75) ""(2821.23,3571.75) ""(2821.49,3556.67) ""(2821.49,3556.67) ""(2821.49,3556.67) ""(2821.49,3556.67) ""(2821.49,3572.01) ""(2821.49,3572.01) ""(2821.49,3572.01) ""(2821.49,3572.01) ""(2821.62,3570.06) ""(2821.62,3570.06) ""(2821.62,3570.06) ""(2821.62,3570.06) ""(2821.62,3570.84) ""(2821.62,3570.84) ""(2821.62,3570.84) ""(2821.62,3570.84) ""(2822.01,3572.53) ""(2822.01,3572.53) ""(2822.01,3572.53) ""(2822.01,3572.53) ""(2822.02,3554.48) ""(2822.02,3554.48) ""(2822.02,3554.48) ""(2822.02,3554.48) ""(2822.14,3560.96) ""(2822.14,3560.96) ""(2822.14,3560.96) ""(2822.14,3560.96) ""(2822.27,3572.53) ""(2822.27,3572.53) ""(2822.27,3572.53) ""(2822.27,3572.53) ""(2822.53,3567.59) ""(2822.53,3567.59) ""(2822.53,3567.59) ""(2822.53,3567.59) ""(2822.53,3575) ""(2822.53,3575) ""(2822.53,3575) ""(2822.53,3575) ""(2822.92,3556.29) ""(2822.92,3556.29) ""(2822.92,3556.29) ""(2822.92,3556.29) ""(2823.05,3572.79) ""(2823.05,3572.79) ""(2823.05,3572.79) ""(2823.05,3572.79) ""(2823.58,3554.36) ""(2823.58,3554.36) ""(2823.59,3554.36) ""(2823.59,3554.36) ""(2824.22,3568.11) ""(2824.22,3568.11) ""(2824.22,3568.11) ""(2824.22,3568.11) ""(2824.22,3572.53) ""(2824.22,3572.53) ""(2824.22,3572.53) ""(2824.22,3572.53) ""(2824.27,3554.35) ""(2824.27,3554.35) ""(2824.27,3554.35) ""(2824.27,3554.35) ""(2824.34,3556.1) ""(2824.34,3556.1) ""(2824.34,3556.1) ""(2824.34,3556.1) ""(2824.35,3561.87) ""(2824.35,3561.87) ""(2824.35,3561.87) ""(2824.35,3561.87) ""(2824.97,3554.38) ""(2824.97,3554.38) ""(2824.97,3554.38) ""(2824.97,3554.38) ""(2825.13,3568.63) ""(2825.13,3568.63) ""(2825.13,3568.63) ""(2825.13,3568.63) ""(2825.13,3572.4) ""(2825.13,3572.4) ""(2825.13,3572.4) ""(2825.13,3572.4) ""(2825.2,3556.13) ""(2825.2,3556.13) ""(2825.65,3575) ""(2825.65,3575) ""(2825.65,3575) ""(2825.65,3575) ""(2825.69,3556.19) ""(2825.69,3556.19) ""(2825.69,3556.19) ""(2825.69,3556.19) ""(2825.78,3571.75) ""(2825.78,3571.75) ""(2825.78,3571.75) ""(2825.78,3571.75) ""(2825.89,3554.43) ""(2825.89,3554.43) ""(2825.89,3554.43) ""(2825.89,3554.43) ""(2825.91,3569.28) ""(2825.91,3569.28) ""(2825.91,3569.28) ""(2825.91,3569.28) ""(2826.04,3570.97) ""(2826.04,3570.97) ""(2826.04,3570.97) ""(2826.04,3570.97) ""(2826.07,3556.31) ""(2826.07,3556.31) ""(2826.07,3556.31) ""(2826.07,3556.31) ""(2826.17,3570.19) ""(2826.17,3570.19) ""(2826.17,3570.19) ""(2826.17,3570.19) ""(2826.43,3562.39) ""(2826.43,3562.39) ""(2826.43,3562.39) ""(2826.43,3562.39) ""(2826.7,3556.51) ""(2826.7,3556.51) ""(2826.7,3556.51) ""(2826.7,3556.51) ""(2826.77,3558.59) ""(2826.77,3558.59) ""(2826.77,3558.59) ""(2826.77,3558.59) ""(2826.77,3558.86) ""(2826.77,3558.86) ""(2826.77,3558.86) ""(2826.77,3558.86) ""(2826.79,3559.23) ""(2826.79,3559.23) ""(2826.79,3559.23) ""(2826.79,3559.23) ""(2826.8,3558.36) ""(2826.8,3558.36) ""(2826.8,3558.36) ""(2826.8,3558.36) ""(2826.89,3559.58) ""(2826.89,3559.58) ""(2826.89,3559.58) ""(2826.89,3559.58) ""(2826.95,3554.47) ""(2826.95,3554.47) ""(2826.95,3554.47) ""(2826.95,3554.47) ""(2827.07,3556.8) ""(2827.07,3556.8) ""(2827.07,3556.8) ""(2827.07,3556.8) ""(2827.09,3559.96) ""(2827.09,3559.96) ""(2827.09,3559.96) ""(2827.09,3559.96) ""(2827.15,3557.91) ""(2827.15,3557.91) ""(2827.15,3557.91) ""(2827.15,3557.91) ""(2827.27,3557.1) ""(2827.27,3557.1) ""(2827.27,3557.78) ""(2827.27,3557.78) ""(2827.27,3557.1) ""(2827.27,3557.1) ""(2827.27,3557.78) ""(2827.27,3557.78) ""(2827.34,3557.53) ""(2827.34,3557.53) ""(2827.34,3557.53) ""(2827.34,3557.53) ""(2827.37,3560.33) ""(2827.37,3560.33) ""(2827.37,3560.33) ""(2827.37,3560.33) ""(2827.82,3560.79) ""(2827.82,3560.79) ""(2827.82,3560.79) ""(2827.82,3560.79) ""(2827.86,3574.35) ""(2827.86,3574.35) ""(2827.86,3574.35) ""(2827.86,3574.35) ""(2828.12,3554.6) ""(2828.12,3554.6) ""(2828.12,3554.6) ""(2828.12,3554.6) ""(2828.19,3561.06) ""(2828.19,3561.06) ""(2828.19,3561.06) ""(2828.19,3561.06) ""(2828.38,3563.43) ""(2828.38,3563.43) ""(2828.38,3563.43) ""(2828.38,3563.43) ""(2828.79,3561.28) ""(2828.79,3561.28) ""(2828.79,3561.28) ""(2828.79,3561.28) ""(2828.87,3554.85) ""(2828.87,3554.85) ""(2828.87,3554.85) ""(2828.87,3554.85) ""(2828.9,3573.44) ""(2828.9,3573.44) ""(2828.9,3573.44) ""(2828.9,3573.44) ""(2829.22,3561.39) ""(2829.22,3561.39) ""(2829.22,3561.39) ""(2829.22,3561.39) ""(2829.56,3555.15) ""(2829.56,3555.15) ""(2829.56,3555.15) ""(2829.56,3555.15) ""(2829.76,3561.39) ""(2829.76,3561.39) ""(2829.76,3561.39) ""(2829.76,3561.39) ""(2830.2,3564.6) ""(2830.2,3564.6) ""(2830.21,3564.6) ""(2830.21,3564.6) ""(2830.33,3572.27) ""(2830.33,3572.27) ""(2830.34,3572.27) ""(2830.34,3572.27) ""(2830.39,3561.33) ""(2830.39,3561.33) ""(2830.39,3561.33) ""(2830.39,3561.33) ""(2830.49,3555.56) ""(2830.49,3555.56) ""(2830.49,3555.56) ""(2830.49,3555.56) ""(2830.92,3561.23) ""(2830.92,3561.23) ""(2830.92,3561.23) ""(2830.92,3561.23) ""(2831.12,3565.25) ""(2831.12,3565.25) ""(2831.12,3565.25) ""(2831.12,3565.25) ""(2831.12,3571.1) ""(2831.12,3571.1) ""(2831.12,3571.1) ""(2831.12,3571.1) ""(2831.19,3555.95) ""(2831.19,3555.95) ""(2831.19,3555.95) ""(2831.19,3555.95) ""(2831.36,3560.96) ""(2831.36,3560.96) ""(2831.36,3560.96) ""(2831.36,3560.96) ""(2831.62,3556.41) ""(2831.62,3556.41) ""(2831.62,3556.41) ""(2831.62,3556.41) ""(2831.64,3566.55) ""(2831.64,3566.55) ""(2831.64,3566.55) ""(2831.64,3566.55) ""(2831.64,3569.8) ""(2831.64,3569.8) ""(2831.64,3569.8) ""(2831.64,3569.8) ""(2831.77,3568.5) ""(2831.77,3568.5) ""(2831.77,3568.5) ""(2831.77,3568.5) ""(2831.83,3560.36) ""(2831.83,3560.36) ""(2831.83,3560.36) ""(2831.83,3560.36) ""(2832.11,3556.96) ""(2832.11,3556.96) ""(2832.11,3556.96) ""(2832.11,3556.96) ""(2832.19,3559.73) ""(2832.19,3559.73) ""(2832.19,3559.73) ""(2832.19,3559.73) ""(2832.28,3557.51) ""(2832.28,3557.51) ""(2832.28,3557.51) ""(2832.28,3557.51) ""(2832.43,3559.11) ""(2832.43,3559.11) ""(2832.43,3559.11) ""(2832.43,3559.11) ""(2835.16,3565.37) ""(2835.16,3565.37) ""(2835.16,3565.37) ""(2835.16,3565.37) ""(2835.16,3567.46) ""(2835.16,3567.46) ""(2835.16,3567.46) ""(2835.16,3567.46) ""(2835.42,3568.63) ""(2835.42,3568.63) ""(2835.42,3568.63) ""(2835.42,3568.63) ""(2835.47,3557.79) ""(2835.47,3557.79) ""(2835.47,3557.79) ""(2835.47,3557.79) ""(2835.72,3558.97) ""(2835.72,3558.97) ""(2835.72,3558.97) ""(2835.72,3558.97) ""(2835.93,3564.6) ""(2835.93,3564.6) ""(2835.93,3564.6) ""(2835.93,3564.6) ""(2836.12,3559.17) ""(2836.12,3559.17) ""(2836.12,3559.17) ""(2836.12,3559.17) ""(2836.59,3556.42) ""(2836.59,3556.42) ""(2836.59,3556.42) ""(2836.59,3556.42) ""(2836.72,3570.97) ""(2836.72,3570.97) ""(2836.72,3570.97) ""(2836.72,3570.97) ""(2836.92,3556.15) ""(2836.92,3556.15) ""(2836.92,3556.15) ""(2836.92,3556.15) ""(2836.98,3559.05) ""(2836.98,3559.05) ""(2836.98,3559.05) ""(2837.62,3555.66) ""(2837.62,3555.66) ""(2837.62,3555.66) ""(2837.62,3555.66) ""(2837.89,3558.23) ""(2837.89,3558.23) ""(2837.89,3558.23) ""(2837.89,3558.23) ""(2838.02,3572.53) ""(2838.02,3572.53) ""(2838.02,3572.53) ""(2838.02,3572.53) ""(2838.3,3555.28) ""(2838.3,3555.28) ""(2838.3,3555.28) ""(2838.3,3555.28) ""(2839.02,3557.21) ""(2839.02,3557.21) ""(2839.02,3557.21) ""(2839.02,3557.21) ""(2839.04,3554.88) ""(2839.04,3554.88) ""(2839.04,3554.88) ""(2839.04,3554.88) ""(2839.19,3573.7) ""(2839.19,3573.7) ""(2839.19,3573.7) ""(2839.19,3573.7) ""(2839.58,3556.85) ""(2839.58,3556.85) ""(2839.58,3556.85) ""(2839.58,3556.85) ""(2840.43,3556.65) ""(2840.43,3556.65) ""(2840.43,3556.65) ""(2840.43,3556.65) ""(2840.49,3574.48) ""(2840.49,3574.48) ""(2840.49,3574.48) ""(2840.49,3574.48) ""(2840.88,3554.44) ""(2840.88,3554.44) ""(2840.88,3554.44) ""(2840.88,3554.44) ""(2841.16,3556.58) ""(2841.16,3556.58) ""(2841.16,3556.58) ""(2841.16,3556.58) ""(2841.27,3567.85) ""(2841.27,3567.85) ""(2841.27,3567.85) ""(2841.27,3567.85) ""(2841.31,3567.6) ""(2841.31,3567.6) ""(2841.31,3567.6) ""(2841.31,3567.6) ""(2841.4,3569.67) ""(2841.4,3569.67) ""(2841.4,3569.67) ""(2841.4,3569.67) ""(2842.07,3566.94) ""(2842.07,3566.94) ""(2842.07,3566.94) ""(2842.07,3566.94) ""(2842.18,3571.49) ""(2842.18,3571.49) ""(2842.18,3571.49) ""(2842.18,3571.49) ""(2842.44,3574.87) ""(2842.44,3574.87) ""(2842.44,3574.87) ""(2842.44,3574.87) ""(2842.96,3572.27) ""(2842.96,3572.27) ""(2842.96,3572.27) ""(2842.96,3572.27) ""(2842.96,3556.61) ""(2842.96,3556.61) ""(2842.97,3556.61) ""(2842.97,3556.61) ""(2843.57,3556.66) ""(2843.57,3556.66) ""(2843.57,3556.66) ""(2843.57,3556.66) ""(2844.07,3556.83) ""(2844.07,3556.83) ""(2844.07,3556.83) ""(2844.07,3556.83) ""(2844.13,3572.53) ""(2844.13,3572.53) ""(2844.13,3572.53) ""(2844.13,3572.53) ""(2844.53,3557.16) ""(2844.53,3557.16) ""(2844.53,3557.16) ""(2844.53,3557.16) ""(2844.65,3554.34) ""(2844.65,3554.34) ""(2844.65,3554.34) ""(2844.65,3554.34) ""(2845.04,3575) ""(2845.04,3575) ""(2845.04,3575) ""(2845.04,3575) ""(2845.08,3557.55) ""(2845.08,3557.55) ""(2845.08,3557.55) ""(2845.08,3557.55) ""(2845.3,3572.53) ""(2845.3,3572.53) ""(2845.3,3572.53) ""(2845.3,3572.53) ""(2845.55,3557.88) ""(2845.55,3557.88) ""(2845.55,3557.88) ""(2845.55,3557.88) ""(2845.96,3558.37) ""(2845.96,3558.37) ""(2845.96,3558.37) ""(2845.96,3558.37) ""(2846.35,3572.01) ""(2846.35,3572.01) ""(2846.35,3572.01) ""(2846.35,3572.01) ""(2846.74,3554.6) ""(2846.74,3554.6) ""(2846.74,3559.79) ""(2846.74,3559.79) ""(2846.74,3554.6) ""(2846.74,3554.6) ""(2846.74,3559.79) ""(2846.74,3559.79) ""(2846.9,3564.6) ""(2846.9,3564.6) ""(2846.9,3564.6) ""(2846.9,3564.6) ""(2847.01,3566.94) ""(2847.01,3566.94) ""(2847.01,3566.94) ""(2847.01,3566.94) ""(2847.13,3570.97) ""(2847.13,3570.97) ""(2847.13,3574.74) ""(2847.13,3574.74) ""(2847.13,3570.97) ""(2847.13,3570.97) ""(2847.13,3574.74) ""(2847.13,3574.74) ""(2847.26,3561.09) ""(2847.26,3561.09) ""(2847.26,3561.09) ""(2847.26,3561.09) ""(2847.52,3562.52) ""(2847.52,3562.52) ""(2847.52,3562.52) ""(2847.52,3562.52) ""(2847.52,3569.54) ""(2847.52,3569.54) ""(2847.52,3569.54) ""(2847.52,3569.54) ""(2847.67,3563.74) ""(2847.67,3563.74) ""(2847.67,3563.74) ""(2847.67,3563.74) ""(2848.43,3555.25) ""(2848.43,3555.25) ""(2848.43,3555.25) ""(2848.43,3555.25) ""(2849.08,3574.22) ""(2849.08,3574.22) ""(2849.08,3574.22) ""(2849.08,3574.22) ""(2850.38,3573.44) ""(2850.38,3573.44) ""(2850.38,3573.44) ""(2850.38,3573.44) ""(2850.51,3556.67) ""(2850.51,3556.67) ""(2850.51,3556.67) ""(2850.51,3556.67) ""(2852.2,3557.97) ""(2852.2,3557.97) ""(2852.2,3557.97) ""(2852.2,3557.97) ""(2852.2,3571.36) ""(2852.2,3571.36) ""(2852.2,3571.36) ""(2852.2,3571.36) ""(2853.24,3559.4) ""(2853.24,3559.4) ""(2853.24,3559.4) ""(2853.24,3559.4) ""(2853.37,3569.67) ""(2853.37,3569.67) ""(2853.37,3569.67) ""(2853.37,3569.67) ""(2854.02,3561.74) ""(2854.02,3561.74) ""(2854.02,3561.74) ""(2854.02,3561.74) ""(2854.02,3568.37) ""(2854.02,3568.37) ""(2854.02,3568.37) ""(2854.02,3568.37) ""(2854.28,3565.25) ""(2854.28,3565.25) ""(2854.28,3565.25) ""(2854.28,3565.25) ""(2857.39,3566.68) ""(2857.39,3566.68) ""(2857.39,3566.68) ""(2857.39,3566.68) ""(2857.52,3570.84) ""(2857.52,3570.84) ""(2857.52,3570.84) ""(2857.52,3570.84) ""(2857.91,3572.92) ""(2857.91,3572.92) ""(2857.91,3572.92) ""(2857.91,3572.92) ""(2858.04,3563.82) ""(2858.04,3563.82) ""(2858.04,3563.82) ""(2858.04,3563.82) ""(2858.56,3575) ""(2858.56,3575) ""(2858.56,3575) ""(2858.56,3575) ""(2859.6,3560.83) ""(2859.6,3560.83) ""(2859.6,3560.83) ""(2859.6,3560.83) ""(2859.6,3577.21) ""(2859.6,3577.21) ""(2859.6,3577.21) ""(2859.6,3577.21) ""(2860.9,3559.27) ""(2860.9,3559.27) ""(2860.9,3559.27) ""(2860.9,3559.27) ""(2861.16,3579.29) ""(2861.16,3579.29) ""(2861.16,3579.29) ""(2861.16,3579.29) ""(2863.24,3580.85) ""(2863.24,3580.85) ""(2863.24,3580.85) ""(2863.24,3580.85) ""(2863.37,3557.2) ""(2863.37,3557.2) ""(2863.37,3557.2) ""(2863.37,3557.2) ""(2864.54,3570.19) ""(2864.54,3570.19) ""(2864.54,3570.19) ""(2864.54,3570.19) ""(2864.8,3565.64) ""(2864.8,3565.64) ""(2864.8,3565.64) ""(2864.8,3565.64) ""(2865.06,3574.48) ""(2865.06,3574.48) ""(2865.06,3574.48) ""(2865.06,3574.48) ""(2865.06,3581.89) ""(2865.06,3581.89) ""(2865.06,3581.89) ""(2865.06,3581.89) ""(2865.2,3562.78) ""(2865.2,3562.78) ""(2865.2,3562.78) ""(2865.2,3562.78) ""(2866.11,3555.64) ""(2866.11,3555.64) ""(2866.11,3555.64) ""(2866.11,3555.64) ""(2866.11,3560.44) ""(2866.11,3560.44) ""(2866.11,3560.44) ""(2866.11,3560.44) ""(2866.24,3577.34) ""(2866.24,3577.34) ""(2866.24,3577.34) ""(2866.24,3577.34) ""(2866.24,3582.28) ""(2866.24,3582.28) ""(2866.24,3582.28) ""(2866.24,3582.28) ""(2867.15,3559.02) ""(2867.15,3559.02) ""(2867.15,3559.02) ""(2867.15,3559.02) ""(2867.93,3579.16) ""(2867.93,3579.16) ""(2867.93,3579.16) ""(2867.93,3579.16) ""(2868.19,3582.8) ""(2868.19,3582.8) ""(2868.19,3582.8) ""(2868.19,3582.8) ""(2868.71,3557.84) ""(2868.71,3557.84) ""(2868.71,3557.84) ""(2868.71,3557.84) ""(2869.13,3554.81) ""(2869.13,3554.81) ""(2869.13,3554.81) ""(2869.13,3554.81) ""(2869.33,3554.78) ""(2869.33,3554.78) ""(2869.33,3554.78) ""(2869.33,3554.78) ""(2869.62,3580.2) ""(2869.62,3580.2) ""(2869.62,3580.2) ""(2869.62,3580.2) ""(2870.01,3582.93) ""(2870.01,3582.93) ""(2870.01,3582.93) ""(2870.01,3582.93) ""(2870.53,3556.94) ""(2870.53,3556.94) ""(2870.53,3556.94) ""(2870.53,3556.94) ""(2870.79,3580.59) ""(2870.79,3580.59) ""(2870.79,3580.59) ""(2870.79,3580.59) ""(2872.09,3580.72) ""(2872.09,3580.72) ""(2872.09,3580.72) ""(2872.09,3580.72) ""(2872.22,3556.67) ""(2872.22,3556.67) ""(2872.22,3556.67) ""(2872.22,3556.67) ""(2874.28,3580.82) ""(2874.28,3580.82) ""(2874.28,3580.82) ""(2874.28,3580.82) ""(2874.34,3556.77) ""(2874.35,3556.77) ""(2874.35,3556.77) ""(2874.35,3556.77) ""(2875.08,3557.54) ""(2875.08,3557.54) ""(2875.08,3557.54) ""(2875.08,3557.54) ""(2875.08,3580.05) ""(2875.08,3580.05) ""(2875.08,3580.05) ""(2875.08,3580.05) ""(2881.7,3557.46) ""(2881.7,3557.46) ""(2881.7,3557.46) ""(2881.7,3557.46) ""(2881.7,3557.59) ""(2881.7,3558.62) ""(2881.7,3580.32) ""(2881.7,3580.32) ""(2881.7,3580.32) ""(2881.7,3580.32) ""(2881.7,3557.59) ""(2881.7,3558.62) ""(2883.09,3582.93) ""(2883.09,3582.93) ""(2883.09,3582.93) ""(2883.09,3582.93) ""(2883.13,3554.78) ""(2883.13,3554.78) ""(2883.13,3554.78) ""(2883.13,3554.78) ""(2884.31,3554.78) ""(2884.31,3554.78) ""(2884.31,3554.78) ""(2884.31,3554.78) ""(2884.31,3557.46) ""(2884.31,3557.46) ""(2884.31,3557.46) ""(2884.31,3557.46) ""(2885.34,3580.32) ""(2885.34,3580.32) ""(2885.34,3580.32) ""(2885.34,3580.32) ""(2885.34,3582.93) ""(2885.34,3582.93) ""(2885.34,3582.93) ""(2885.34,3582.93)
  round 8.82 on Bottom Overlay: ""(2641.78,3581.73)
  round 8.65 on Bottom Overlay: ""(2808.37,3582)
